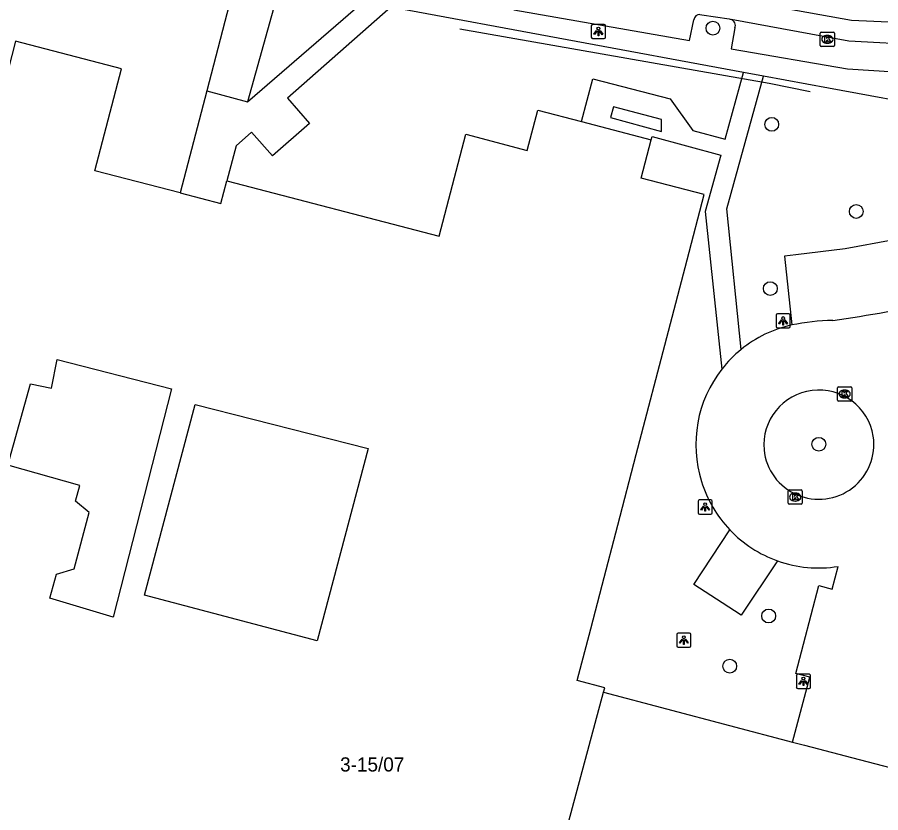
# Model space of a CAD drawing. Extents: x 163686 to 164493, y 382719 to 383870.
# Drawn here: x 164044.5 to 164105.5, y 383311.7 to 383368 of the extents above; entities that cross this region are included whole.
import ezdxf

# ---------------------------------------------------------------- set-up
doc = ezdxf.new("R2010")
doc.units = 0
for name, color, linetype in [('IMGEO_Boom', 7, 'Continuous'), ('IMGEO_Groenvoorziening', 7, 'Continuous'), ('IMGEO_Kolk', 7, 'Continuous'), ('IMGEO_Lichtpunt', 7, 'Continuous'), ('IMGEO_Muur', 7, 'Continuous'), ('IMGEO_Pand', 7, 'Continuous'), ('IMGEO_Pand_nummerreeks', 7, 'Continuous'), ('IMGEO_Parkeervlak_open', 7, 'Continuous'), ('IMGEO_Rijbaan_lokaal_open', 7, 'Continuous'), ('IMGEO_Voetpad_op_trap', 7, 'Continuous'), ('IMGEO_Voetpad_open', 7, 'Continuous')]:
    doc.layers.add(name, color=color, linetype=linetype)

msp = doc.modelspace()

# ---------------------------------------------------------------- linework, layer by layer
at = {"layer": 'IMGEO_Boom'}
for centre in [(164093.617, 383367.203), (164097.771, 383360.403), (164103.745, 383354.247), (164097.67, 383348.79), (164101.098, 383337.783), (164097.554, 383325.641), (164094.804, 383322.096)]:
    msp.add_circle(centre, 0.489, dxfattribs=at)
at = {"layer": 'IMGEO_Groenvoorziening'}
msp.add_lwpolyline([(164098.184, 383329.537), (164095.615, 383325.69), (164094.261, 383326.572), (164092.275, 383327.866), (164094.815, 383331.726)], dxfattribs=at)
at = {"layer": 'IMGEO_Kolk'}
for p, q in [((164101.201, 383365.989), (164101.201, 383366.841)), ((164101.276, 383366.915), (164102.128, 383366.915)), ((164101.689, 383366.695), (164101.714, 383366.695)), ((164102.202, 383366.841), (164102.202, 383365.989)), ((164102.128, 383365.915), (164101.276, 383365.915)), ((164101.712, 383366.135), (164101.687, 383366.135)), ((164102.422, 383340.912), (164102.422, 383341.764)), ((164102.497, 383341.838), (164103.349, 383341.838)), ((164102.91, 383341.618), (164102.935, 383341.618)), ((164103.423, 383341.764), (164103.423, 383340.912)), ((164103.349, 383340.838), (164102.497, 383340.838)), ((164102.933, 383341.058), (164102.908, 383341.058)), ((164098.931, 383333.623), (164098.931, 383334.475)), ((164099.006, 383334.549), (164099.858, 383334.549)), ((164099.419, 383334.329), (164099.444, 383334.329)), ((164099.932, 383334.475), (164099.932, 383333.623)), ((164099.858, 383333.549), (164099.006, 383333.549)), ((164099.442, 383333.769), (164099.417, 383333.769))]:
    msp.add_line(p, q, dxfattribs=at)
for points in [[(164101.201, 383365.989), (164101.201, 383366.841)], [(164101.276, 383366.915), (164102.128, 383366.915)], [(164101.522, 383366.615), (164101.645, 383366.615), (164101.645, 383366.464), (164101.775, 383366.615), (164101.939, 383366.615), (164101.793, 383366.464), (164101.946, 383366.215), (164101.794, 383366.215), (164101.709, 383366.379), (164101.645, 383366.312), (164101.645, 383366.215), (164101.522, 383366.215), (164101.522, 383366.615)], [(164102.202, 383366.841), (164102.202, 383365.989)], [(164102.128, 383365.915), (164101.276, 383365.915)], [(164102.422, 383340.912), (164102.422, 383341.764)], [(164102.497, 383341.838), (164103.349, 383341.838)], [(164102.743, 383341.538), (164102.866, 383341.538), (164102.866, 383341.387), (164102.996, 383341.538), (164103.16, 383341.538), (164103.014, 383341.387), (164103.167, 383341.138), (164103.015, 383341.138), (164102.93, 383341.302), (164102.866, 383341.235), (164102.866, 383341.138), (164102.743, 383341.138), (164102.743, 383341.538)], [(164103.423, 383341.764), (164103.423, 383340.912)], [(164103.349, 383340.838), (164102.497, 383340.838)], [(164098.931, 383333.623), (164098.931, 383334.475)], [(164099.006, 383334.549), (164099.858, 383334.549)], [(164099.252, 383334.249), (164099.375, 383334.249), (164099.375, 383334.098), (164099.505, 383334.249), (164099.669, 383334.249), (164099.523, 383334.098), (164099.676, 383333.849), (164099.524, 383333.849), (164099.439, 383334.013), (164099.375, 383333.946), (164099.375, 383333.849), (164099.252, 383333.849), (164099.252, 383334.249)], [(164099.932, 383334.475), (164099.932, 383333.623)], [(164099.858, 383333.549), (164099.006, 383333.549)]]:
    msp.add_lwpolyline(points, dxfattribs=at)
for centre, start, end in [((164101.278, 383366.839), 91.55205, 178.44795), ((164101.278, 383366.839), 91.55205, 178.44795), ((164102.126, 383366.839), 1.55205, 88.44795), ((164102.126, 383366.839), 1.55205, 88.44795), ((164101.278, 383365.991), 181.55205, 268.44795), ((164101.278, 383365.991), 181.55205, 268.44795), ((164102.126, 383365.991), 271.55205, 358.44795), ((164102.126, 383365.991), 271.55205, 358.44795), ((164102.499, 383341.762), 91.55205, 178.44795), ((164102.499, 383341.762), 91.55205, 178.44795), ((164103.347, 383341.762), 1.55205, 88.44795), ((164103.347, 383341.762), 1.55205, 88.44795), ((164102.499, 383340.914), 181.55205, 268.44795), ((164102.499, 383340.914), 181.55205, 268.44795), ((164103.347, 383340.914), 271.55205, 358.44795), ((164103.347, 383340.914), 271.55205, 358.44795), ((164099.008, 383334.473), 91.55205, 178.44795), ((164099.008, 383334.473), 91.55205, 178.44795), ((164099.856, 383334.473), 1.55205, 88.44795), ((164099.856, 383334.473), 1.55205, 88.44795), ((164099.008, 383333.625), 181.55205, 268.44795), ((164099.008, 383333.625), 181.55205, 268.44795), ((164099.856, 383333.625), 271.55205, 358.44795), ((164099.856, 383333.625), 271.55205, 358.44795)]:
    msp.add_arc(centre, 0.0765, start, end, dxfattribs=at)
for centre, major_axis, ratio, start_param, end_param in [((164101.688, 383366.415), (-0.387, 0.002), 0.722429, 4.712389, 7.853982), ((164101.713, 383366.415), (-0.39, 0.002), 0.717154, 1.570796, 4.712389), ((164102.909, 383341.338), (-0.387, 0.002), 0.722429, 4.712389, 7.853982), ((164102.934, 383341.338), (-0.39, 0.002), 0.717154, 1.570796, 4.712389), ((164099.418, 383334.049), (-0.387, 0.002), 0.722429, 4.712389, 7.853982), ((164099.443, 383334.049), (-0.39, 0.002), 0.717154, 1.570796, 4.712389)]:
    msp.add_ellipse(centre, major_axis=major_axis, ratio=ratio, start_param=start_param, end_param=end_param, dxfattribs=at)
at = {"layer": 'IMGEO_Lichtpunt'}
for p, q in [((164085.023, 383367.372), (164085.023, 383366.565)), ((164085.023, 383367.372), (164085.023, 383366.565)), ((164085.925, 383367.467), (164085.117, 383367.467)), ((164085.925, 383367.467), (164085.117, 383367.467)), ((164086.019, 383366.565), (164086.019, 383367.372)), ((164086.019, 383366.565), (164086.019, 383367.372)), ((164085.117, 383366.471), (164085.925, 383366.471)), ((164085.117, 383366.471), (164085.925, 383366.471)), ((164098.076, 383346.91), (164098.076, 383346.103)), ((164098.076, 383346.91), (164098.076, 383346.103)), ((164098.978, 383347.005), (164098.17, 383347.005)), ((164098.978, 383347.005), (164098.17, 383347.005)), ((164099.072, 383346.103), (164099.072, 383346.91)), ((164099.072, 383346.103), (164099.072, 383346.91)), ((164098.17, 383346.009), (164098.978, 383346.009)), ((164098.17, 383346.009), (164098.978, 383346.009)), ((164092.573, 383333.749), (164092.573, 383332.942)), ((164092.573, 383333.749), (164092.573, 383332.942)), ((164093.475, 383333.844), (164092.667, 383333.844)), ((164093.475, 383333.844), (164092.667, 383333.844)), ((164093.569, 383332.942), (164093.569, 383333.749)), ((164093.569, 383332.942), (164093.569, 383333.749)), ((164092.667, 383332.848), (164093.475, 383332.848)), ((164092.667, 383332.848), (164093.475, 383332.848)), ((164091.064, 383324.336), (164091.064, 383323.529)), ((164091.064, 383324.336), (164091.064, 383323.529)), ((164091.966, 383324.431), (164091.158, 383324.431)), ((164091.966, 383324.431), (164091.158, 383324.431)), ((164092.06, 383323.529), (164092.06, 383324.336)), ((164092.06, 383323.529), (164092.06, 383324.336)), ((164091.158, 383323.435), (164091.966, 383323.435)), ((164091.158, 383323.435), (164091.966, 383323.435)), ((164099.51, 383321.421), (164099.51, 383320.614)), ((164099.51, 383321.421), (164099.51, 383320.614)), ((164100.412, 383321.516), (164099.604, 383321.516)), ((164100.412, 383321.516), (164099.604, 383321.516)), ((164100.506, 383320.614), (164100.506, 383321.421)), ((164100.506, 383320.614), (164100.506, 383321.421)), ((164099.604, 383320.52), (164100.412, 383320.52)), ((164099.604, 383320.52), (164100.412, 383320.52))]:
    msp.add_line(p, q, dxfattribs=at)
for points in [[(164085.397, 383367.036), (164085.436, 383367.008), (164085.248, 383366.746), (164085.21, 383366.773), (164085.397, 383367.036)], [(164085.499, 383366.988), (164085.546, 383366.988), (164085.546, 383366.666), (164085.499, 383366.666), (164085.499, 383366.988)], [(164085.609, 383367.008), (164085.647, 383367.035), (164085.834, 383366.773), (164085.795, 383366.745), (164085.609, 383367.008)], [(164098.45, 383346.574), (164098.489, 383346.546), (164098.301, 383346.284), (164098.263, 383346.311), (164098.45, 383346.574)], [(164098.552, 383346.526), (164098.599, 383346.526), (164098.599, 383346.204), (164098.552, 383346.204), (164098.552, 383346.526)], [(164098.662, 383346.546), (164098.7, 383346.573), (164098.887, 383346.311), (164098.848, 383346.283), (164098.662, 383346.546)], [(164092.947, 383333.413), (164092.986, 383333.385), (164092.798, 383333.123), (164092.76, 383333.15), (164092.947, 383333.413)], [(164093.049, 383333.365), (164093.096, 383333.365), (164093.096, 383333.043), (164093.049, 383333.043), (164093.049, 383333.365)], [(164093.159, 383333.385), (164093.197, 383333.412), (164093.384, 383333.15), (164093.345, 383333.122), (164093.159, 383333.385)], [(164091.438, 383324), (164091.477, 383323.972), (164091.289, 383323.71), (164091.251, 383323.737), (164091.438, 383324)], [(164091.54, 383323.952), (164091.587, 383323.952), (164091.587, 383323.63), (164091.54, 383323.63), (164091.54, 383323.952)], [(164091.65, 383323.972), (164091.688, 383323.999), (164091.875, 383323.737), (164091.836, 383323.709), (164091.65, 383323.972)], [(164099.884, 383321.085), (164099.923, 383321.057), (164099.735, 383320.795), (164099.697, 383320.822), (164099.884, 383321.085)], [(164099.986, 383321.037), (164100.033, 383321.037), (164100.033, 383320.715), (164099.986, 383320.715), (164099.986, 383321.037)], [(164100.096, 383321.057), (164100.134, 383321.084), (164100.321, 383320.822), (164100.282, 383320.794), (164100.096, 383321.057)]]:
    msp.add_lwpolyline(points, dxfattribs=at)
for centre in [(164085.522, 383367.17), (164098.575, 383346.708), (164093.072, 383333.547), (164091.563, 383324.134), (164100.009, 383321.219)]:
    msp.add_circle(centre, 0.0994, dxfattribs=at)
for centre, start, end in [((164085.117, 383367.372), 90, 180), ((164085.117, 383367.372), 90, 180), ((164085.925, 383367.372), 0, 90), ((164085.925, 383367.372), 0, 90), ((164085.117, 383366.565), 180, 270), ((164085.117, 383366.565), 180, 270), ((164085.925, 383366.565), 270, 0), ((164085.925, 383366.565), 270, 360), ((164098.17, 383346.91), 90, 180), ((164098.17, 383346.91), 90, 180), ((164098.978, 383346.91), 0, 90), ((164098.978, 383346.91), 0, 90), ((164098.17, 383346.103), 180, 270), ((164098.17, 383346.103), 180, 270), ((164098.978, 383346.103), 270, 0), ((164098.978, 383346.103), 270, 360), ((164092.667, 383333.749), 90, 180), ((164092.667, 383333.749), 90, 180), ((164093.475, 383333.749), 0, 90), ((164093.475, 383333.749), 0, 90), ((164092.667, 383332.942), 180, 270), ((164092.667, 383332.942), 180, 270), ((164093.475, 383332.942), 270, 0), ((164093.475, 383332.942), 270, 360), ((164091.158, 383324.336), 90, 180), ((164091.158, 383324.336), 90, 180), ((164091.966, 383324.336), 0, 90), ((164091.966, 383324.336), 0, 90), ((164091.158, 383323.529), 180, 270), ((164091.158, 383323.529), 180, 270), ((164091.966, 383323.529), 270, 0), ((164091.966, 383323.529), 270, 360), ((164099.604, 383321.421), 90, 180), ((164099.604, 383321.421), 90, 180), ((164100.412, 383321.421), 0, 90), ((164100.412, 383321.421), 0, 90), ((164099.604, 383320.614), 180, 270), ((164099.604, 383320.614), 180, 270), ((164100.412, 383320.614), 270, 0), ((164100.412, 383320.614), 270, 360)]:
    msp.add_arc(centre, 0.0946, start, end, dxfattribs=at)
at = {"layer": 'IMGEO_Muur'}
msp.add_lwpolyline([(164100.487, 383362.697), (164097.584, 383363.289), (164075.744, 383367.128)], dxfattribs=at)
at = {"layer": 'IMGEO_Pand'}
for points in [[(164055.97, 383355.556), (164049.956, 383357.124), (164051.836, 383364.333), (164044.35, 383366.286), (164043.535, 383363.162), (164041.881, 383363.594), (164042.696, 383366.716), (164035.392, 383368.622), (164028.181, 383340.768), (164029.425, 383340.444), (164029.28, 383339.888), (164028.155, 383336.236), (164028.923, 383336.029), (164027.508, 383330.586), (164028.774, 383330.255), (164025.095, 383316.026), (164024.106, 383312.203), (164022.855, 383312.523), (164022.829, 383312.424)], [(164059.275, 383356.399), (164074.274, 383352.489), (164076.153, 383359.698), (164080.494, 383358.566), (164081.235, 383361.409), (164084.334, 383360.601)], [(164084.334, 383360.601), (164089.257, 383359.317)], [(164085.894, 383320.243), (164085.979, 383320.57), (164084.031, 383321.078), (164084.983, 383324.731), (164085.786, 383327.81), (164086.894, 383332.059), (164088.199, 383337.063), (164090.469, 383345.772), (164091.788, 383350.832), (164092.991, 383355.446), (164088.549, 383356.605), (164089.257, 383359.317)], [(164055.97, 383355.556), (164058.859, 383354.803), (164059.275, 383356.399)], [(164099.232, 383316.726), (164100.092, 383316.499), (164103.954, 383315.494), (164107.919, 383314.448), (164108.893, 383327.316), (164144.967, 383335.071), (164142.367, 383356.094), (164142.394, 383356.096)], [(164051.251, 383325.548), (164046.759, 383326.908), (164047.227, 383328.605), (164048.477, 383328.967), (164049.543, 383332.965), (164048.57, 383333.762), (164048.883, 383334.875), (164043.79, 383336.308), (164045.406, 383342.047), (164046.878, 383341.754), (164047.281, 383343.777), (164055.362, 383341.703), (164051.251, 383325.548)], [(164053.467, 383327.107), (164057.042, 383340.592), (164069.256, 383337.484), (164065.648, 383323.877), (164053.467, 383327.107)], [(164081.08, 383302.369), (164085.894, 383320.243)], [(164085.894, 383320.243), (164099.232, 383316.726)]]:
    msp.add_lwpolyline(points, dxfattribs=at)
at = {"layer": 'IMGEO_Parkeervlak_open'}
msp.add_lwpolyline([(164106.284, 383352.215), (164102.964, 383351.593), (164099.486, 383351.185), (164098.662, 383351.088), (164099.189, 383346.216)], dxfattribs=at)
at = {"layer": 'IMGEO_Rijbaan_lokaal_open'}
for points in [[(164038.521, 383377.899), (164038.786, 383379.375), (164103.399, 383367.78), (164109.713, 383367.482), (164198.705, 383365.887), (164205.201, 383365.177), (164213.958, 383363.713), (164230.957, 383359.822), (164242.9, 383358.082)], [(164092.699, 383368.174), (164092.839, 383368.148), (164094.762, 383367.853), (164094.896, 383367.828)], [(164108.463, 383366.001), (164103.227, 383366.287), (164094.896, 383367.828)], [(164099.232, 383316.726), (164100.47, 383321.305), (164099.476, 383321.565), (164101.098, 383327.801), (164102.05, 383327.544), (164102.457, 383329.149)]]:
    msp.add_lwpolyline(points, dxfattribs=at)
for centre, radius, start, end in [((164085.781, 383460.331), 114.953, 278.15313, 285.77937), ((164101.06, 383337.775), 8.646, 102.49902, 129.13878), ((164102.493, 383329.79), 16.755, 91.40248, 101.37351), ((164101.031, 383337.801), 8.608, 129.09678, 141.99294), ((164101.057, 383337.77), 8.647, 141.93639, 197.60622), ((164101.106, 383337.723), 3.895, 9.41073, 184.99634), ((164101.098, 383337.783), 3.893, 185.88409, 8.52298), ((164101.054, 383337.664), 8.613, 196.94053, 223.58065), ((164101.057, 383337.645), 8.602, 223.48164, 250.49095), ((164101.076, 383337.661), 8.623, 250.40656, 279.21667)]:
    msp.add_arc(centre, radius, start, end, dxfattribs=at)
at = {"layer": 'IMGEO_Voetpad_op_trap'}
for points in [[(164059.919, 383370.702), (164057.849, 383362.762)], [(164063.001, 383370.132), (164060.731, 383361.984)]]:
    msp.add_lwpolyline(points, dxfattribs=at)
at = {"layer": 'IMGEO_Voetpad_open'}
for points in [[(164079.781, 383369.982), (164079.559, 383368.505), (164091.968, 383366.326), (164092.259, 383367.789)], [(164060.731, 383361.984), (164068.882, 383369.045)], [(164070.848, 383368.682), (164063.55, 383362.263), (164065.124, 383360.474), (164062.506, 383358.171), (164061.027, 383359.852), (164059.922, 383358.88), (164059.275, 383356.399)], [(164095.779, 383364.072), (164070.848, 383368.682)], [(164095.166, 383367.22), (164094.901, 383365.747), (164103.12, 383364.326), (164107.955, 383364.013), (164107.904, 383365.522)], [(164084.334, 383360.601), (164085.124, 383363.629), (164090.594, 383362.202), (164092.186, 383359.979), (164094.474, 383359.347), (164095.779, 383364.072)], [(164097.196, 383363.81), (164095.779, 383364.072)], [(164095.603, 383344.481), (164094.607, 383354.438), (164097.196, 383363.81)], [(164114.816, 383361.369), (164109.721, 383361.495), (164101.776, 383362.963), (164097.196, 383363.81)], [(164057.849, 383362.762), (164055.97, 383355.556)], [(164057.849, 383362.762), (164060.731, 383361.984)], [(164086.388, 383360.878), (164089.986, 383359.889), (164089.986, 383360.753), (164086.587, 383361.64), (164086.388, 383360.878)], [(164089.257, 383359.317), (164089.319, 383359.554), (164094.165, 383358.221), (164093.072, 383354.249), (164094.249, 383343.101)]]:
    msp.add_lwpolyline(points, dxfattribs=at)
for centre, radius, start, end in [((164092.691, 383367.74), 0.434, 88.89223, 173.47962), ((164094.75, 383367.399), 0.453, 336.69358, 71.19642)]:
    msp.add_arc(centre, radius, start, end, dxfattribs=at)

# ---------------------------------------------------------------- texts
at = {"layer": 'IMGEO_Pand_nummerreeks'}
msp.add_text('3-15/07', height=1, rotation=360, dxfattribs=at).set_placement((164067.278, 383314.644))

doc.saveas('drawing.dxf')
